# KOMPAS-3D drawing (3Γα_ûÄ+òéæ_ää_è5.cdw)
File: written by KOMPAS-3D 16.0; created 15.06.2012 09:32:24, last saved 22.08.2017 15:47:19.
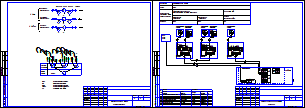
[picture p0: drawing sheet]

Sheets 1-2: A3, landscape

Title block, sheet 1: name: г. Москва, ул. Нежинская, д. 14, к.8 (кв. 1 и кв. 2); sheet number: 1; sheets: 27 / 28; sheet format: A3; stored path: D:\Проекты\Лыткарино\ул. Квартал 3А, д.25\710.74 РП.cdw; cell 320: Р
Title block, sheet 2: sheet number: 2

Views: Вид 2, Вид 3, Вид 4, Вид 5
Referenced files in C:\Program Files (x86)\ASCON\KOMPAS-3D V16\Sys\: SPDS.lcs, EngSys.lcs, GRAPHIC.LHS
Referenced files: graphic.tdp
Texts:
  МО, Клинский район, д. Решетниково, ул. Центральная, д.14
  GOST Common
  Normal
  List Paragraph
  heading 3
  для схемы
  txt
  краны
  Фоновая заливка
  Т0-элементы
  ВРУ
  каб.
  Начало
  трассы
  Трассы
  Марка
  Проложен
  Датчик температуры (Т1)
  Датчик температуры (Т2)
  Датчик давления (Т1)
  Датчик давления (Т2)
  Изм. модуль (Т2)
  Изм. модуль (Т1)
  Изм. модуль (В1)
  ВРУ 220В, 50 Гц
  ИМ1 УУТЭ
  ИМ2 УУТЭ
  ИМ (Т1)
  СБ МКТС
  FTP
  ПВС
  Конец
  Кол-во и
  сеч. жил
  Длина,
  Агрегат
  Системный блок  МКТС
  Среда
  Вода
  параметра и место
  отбора импульса
  Учет тепловой энергии и
  теплоносителя системы отопления
  Подающий
  трубопровод
  отопления
  Обратный
  Узел учета ХВС
  Вводной
  трубопровод ХВС
  ИМ1
  ИМ2
  ИМ3
  Плата подключений
  Pt 100
  Преобразователь
  температуры
  давления
  UP+
  UP-
  ИМП
  Лин
  Измерительный
  модуль М121
  Преобразователь расхода
  Термопреобразователь
  Преобразователь давления
  Преобразователь цифровой
  Системный блок МКТС
  приборы
  по месту
  шкаф
  учета
  UQIES
  УУТЭ
  Функциональная схема
  УУХВС
  Размеры, параметризация
  сит. план
  подача ГВС
  обратка ГВС
  хвс
  обратка
  POLYLINE_STYLE_0.25_RGB_0_0_0
  стены
  Основная (не является границей для штриховки)
  POLYLINE_STYLE_0.18_RGB_0_0_0
  ХВС
  зеленая
  Красная тонкая
  арматура
  Подача
  Скрытая линия
  Ось Z
  Ось Y
  Ось X
  Образующая трубопровода (проектируемого)
  Трубопровод толщиной 0.6мм (одна линия)
  Трубопровод толщиной 1.2мм (одна линия)
  Трубопровод толщиной 1.0мм (одна линия)
  Трубопровод толщиной 0.8мм (одна линия)
  Трубопровод существующий (одна линия)
  Трубопровод невидимый (одна линия)
  Трубопровод демонтируемый (одна линия)
  Осевая трубопровода
  Осевая трубопровода (демонтируемого)
  Образующая трубопровода (существующего)
  Образующая трубопровода (невидимого)
  Изолированный трубопровод проектируемый (одна линия)
  Изолированный трубопровод существующий (одна линия)
  Образующая изоляции
  Изоляция
  Изолированный трубопровод невидимый (одна линия)
  Штрих пвс 075
  штрих пвс 2,5
  существующее оборудование
  Существующее оборудование
  K5LT_BASIC_RGB_0_0_255_THICK_0.53
  POLYLINE_STYLE_1.51_RGB_0_0_255
  POLYLINE_STYLE_0.50_RGB_128_128_128
  K5LT_AXLED_RGB_255_128_0_SC_1_THICK_0.18
  ACAD_ISO04W100_RGB_0_0_0_SC_1_THICK_0.18
  тонкая черная
  пломбировка
  Провода
  синий штрих
  Стили документа
  G2co
  расход вторичной воды объемный
  расход вторичной воды объемный при 70гр
  Gco
  расход теплоносителя массовый
  расход теплоносит объемн подающ
  расход теплоносит объемн обр
  Лапир
  Ghvs
  Im1
  Im2
  Im3
  Im4
  Im5
  Khvs
  норматив ХВС
  число подъездов
  число этажей
  Nkv
  число квартир
  тепловая нагрузка на отопление
  сумма Q
  Qgvs
  тепловая нагрузка ГВС
  тепловая нагрузка на циркуляцию ГВС
  иммитовставка или под манометр
  ro1
  ro2
  ro3
  ro4
  верх предел темп граф
  нижн предел темп граф
  темп подачи ГВС
  темп обр ГВС
  темр хол воды
  vzdh
  Kchn
  Ktp
  Knp
  beta
  tnv
  Vклап
  KLP
  RPD
  RDS
  PUMP
  ro5
  Переход К-76 x 3-38 x 2-09Г2С ГОСТ 17378-2001
  Переход ГОСТ 17378-2001
  Переход
  ГОСТ
  Сталь 09Г2С ГОСТ 19281-89
  Переход К-76 x 3-45 x 2,5-09Г2С ГОСТ 17378-2001
  Переход К-57 x 3-38 x 2-09Г2С ГОСТ 17378-2001
  Переход К-57 x 3-32 x 2-09Г2С ГОСТ 17378-2001
  Втулка 20x50
  Переход К-108 x 4-57 x 3-09Г2С ГОСТ 17378-2001
  Переход К-45 x 2,5-32 x 2-09Г2С ГОСТ 17378-2001
  Переход К-89 x 3,5-45 x 2,5-09Г2С ГОСТ 17378-2001
  Переход К-133 x 5-108 x 4-09Г2С ГОСТ 17378-2001
  Переход К-159 x 4,5-89 x 3,5-09Г2С ГОСТ 17378-2001
  Переход К-45 x 2,5-38 x 2-09Г2С ГОСТ 17378-2001
  Фланец 1-32-1 Ст3сп ГОСТ 12820-80
  Фланцы
  Фланец
  квадратный
  Ст3сп
  Ст3сп ГОСТ 380-2005
  Переход К-57 x 3-45 x 2,5-09Г2С ГОСТ 17378-2001
  Переход К-76 x 3-57 x 3-09Г2С ГОСТ 17378-2001
  Фланец 1-50-16 Ст3сп ГОСТ 12821-80
  Переход К-89 x 3,5-76 x 3,5-09Г2С ГОСТ 17378-2001
  Переход К-108 x 4-89 x 3,5-09Г2С ГОСТ 17378-2001
  Тройник 159 x 4,5-09Г2С ГОСТ 17376-2001
  Тройники ГОСТ 17376-2001
  Тройник
  Отвод 90-159 x 4-09Г2С ГОСТ 17375-2001
  Отвод ГОСТ 17375-2001
  Отвод
  Переход К-108 x 4-76 x 3,5-09Г2С ГОСТ 17378-2001
  Переход К-159 x 4,5-108 x 4-09Г2С ГОСТ 17378-2001
  Переход К-133 x 5-76 x 3,5-09Г2С ГОСТ 17378-2001
  Переход К-133 x 4-89 x 3,5-09Г2С ГОСТ 17378-2001
  Переход К-1-42,4 x 2,6-21,3 x 2-TS10 ГОСТ 17378-2001
  TS10
  Сталь TS10 ИСО 2604/2-75
  Фланец 1-20-16 Ст3сп ГОСТ 12820-80
  Лит-Масса-Масштаб
  Материал-Предприятие
  Title Specification
  Body Specification ( left align )
  Body Specificaton ( centered )
  Поз.
  Кол.
  Приме-
  чание
  Таблица спецификации
  Засыпка
  Штрих3
  Штрих2
  Штрих1
  Песок
  Штр0.5пр7
  Штр0.5пр12
  Штр0.3пр10
  Штр1.4пр21.21
  Штр1пр15
  Штр2.12пр35
  Штр1.5пр25
  Штр2.82пр42.42
  Штр2пр30
  SACNCR_ISO 1
  Электрощитовая
  Пр-1
  Ок-1
  вапвыапвы
  Обозначение стандарта
  Типоразмер
  Разраб.
  Пров.
  Т.контр.
  Н.контр.
  Утв.
  автоматизации
  Рабочие чертежи основного комплекта. ГОСТ Р 21.1101-2009 Ф3
  Стадия
  Лист
  Листов
  Изм.
  Кол.уч.
  №док.
  Подп.
  Дата
  Изменение
  Номер документа
  Подпись
  Наименование объекта строительства, в состав которого входит здание, наим. микр
  Наименование здания (сооружения)
  Порядковый номер листа
  Количество листов в документе
  Наименование изображения
  Индекс предприятия, выпускающего документ
  Инв. № подл.
  Подп. и дата
  Взам. инв. №
  Инвентарный номер подлинника
  Подпись принявшего подлинник на хранение
  Инвентарный номер подлинника, взамен которого выпущен данный подлинник
  Согласовано
  Формат листа
  Согласование
  03 Рабочие чертежи основного комплекта. ГОСТ Р 21.1101-2009 Ф3
  Схема соединений внешних
  проводок
Dimensions and other numbers on the sheet: 0; 220В; 50Гц; 2x2x0,52; 3х0,75; 1; 2; 15; 14; 25; 3; 6; 5; 4; 4-20; 12; 1,2,3; 4,5; 6,7,8; 9,10,11; 7; 9; 10; 11; 4,0; 2,6582; 0,0160; 16; 95; 2,6160; 3,0; 70; 8; 0,0; 0,0000; 09Г2С; 17; 19; 20; 21; 22; 23; 24; 26; 30; 31; 33; 34; 52; 64; 65; 66; 67; 69; 71; 72; 73; 74; 75; 27; 28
